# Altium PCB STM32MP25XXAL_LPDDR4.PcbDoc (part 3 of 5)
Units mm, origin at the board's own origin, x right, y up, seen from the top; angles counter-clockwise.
Board outline 125 x 95 mm, 6 copper layers (Top Layer, Signal Layer 1, Signal Layer 2, Signal Layer 3, Signal Layer 4, Bottom Layer), stack 1.403 mm thick; 182 components, 297 nets, 1131 pads, 958 vias.
Unrouted connection lines stored in the file: 5.
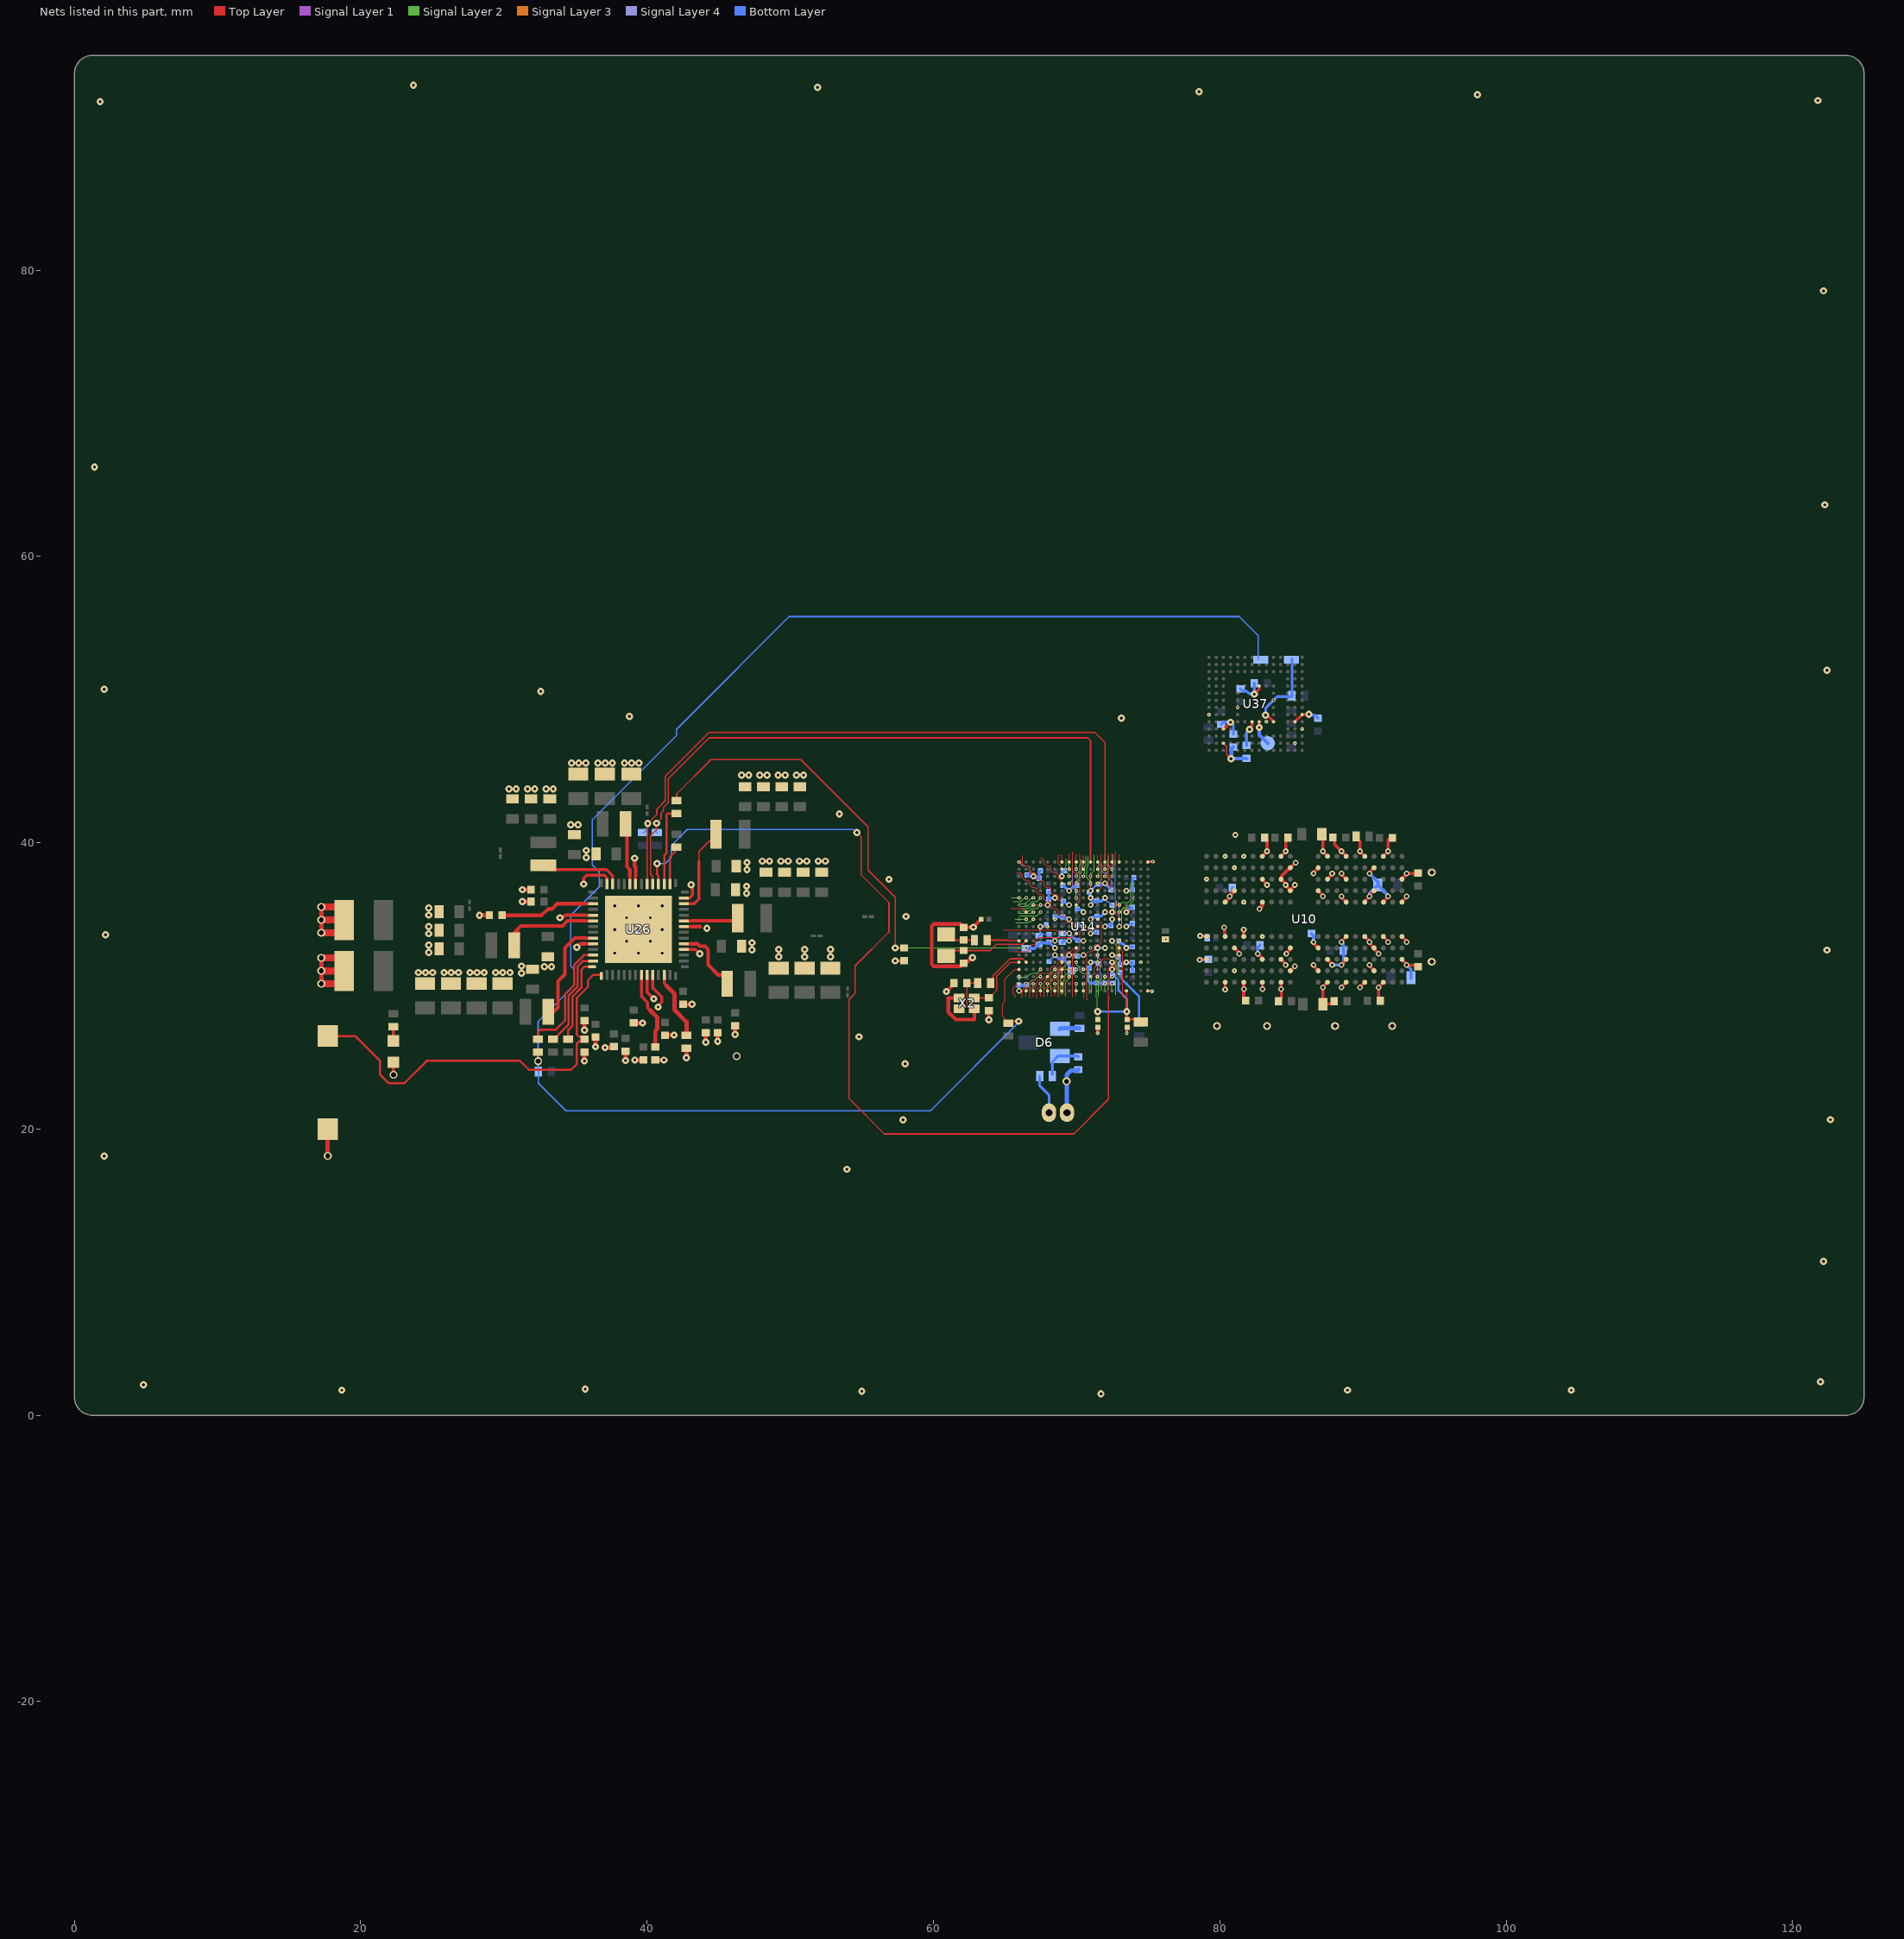
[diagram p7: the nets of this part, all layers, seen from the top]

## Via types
v1: diameter 0.26, hole 0.1, Top Layer to Signal Layer 1, 266 vias
v2: diameter 0.5, hole 0.2, Top Layer to Bottom Layer, 216 vias
v3: diameter 0.26, hole 0.1, Signal Layer 1 to Signal Layer 2, 138 vias
v4: diameter 0.4, hole 0.2, Signal Layer 1 to Signal Layer 4, 99 vias
v5: diameter 0.4, hole 0.2, Top Layer to Bottom Layer, tented both sides, 94 vias
v6: diameter 0.26, hole 0.1, Signal Layer 4 to Bottom Layer, 82 vias
v7: diameter 0.55, hole 0.35, Top Layer to Bottom Layer, 55 vias
v8: diameter 0.55, hole 0.3, Top Layer to Bottom Layer, 7 vias
v9: diameter 0.5, hole 0.2, Signal Layer 1 to Signal Layer 4, 1 vias

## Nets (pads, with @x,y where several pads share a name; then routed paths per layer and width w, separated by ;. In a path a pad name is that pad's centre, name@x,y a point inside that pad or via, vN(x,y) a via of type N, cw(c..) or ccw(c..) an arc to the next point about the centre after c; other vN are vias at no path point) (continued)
GND: B2.1 C1.1 C2.1 C3.1 C4.1 C5.1 C9.1 C14.1 C15.1 C16.1 C17.1 C18.2 C19.1 C20.1 C21.1 C22.1 C23.1 C24.1 C26.1 C27.1 C28.1 C29.1 C30.1 C32.1 C33.1 C34.1 C35.1 C36.1 C37.1 C38.1 C39.1 C40.1 C41.1 C42.2 C43.1 C50.1 C51.1 C52.1 C53.2 C54.2 C55.2 C56.2 C57.2 C58.2 C59.2 C60.2 C61.2 C62.1 C63.1 C64.1 C65.1 C66.1 C67.1 C68.1 C79.1 C81.2 C86.2 C87.1 C90.1 C91.2 C92.2 C117.1 C118.1 C128.1 C130.1 C141.2 C142.2 C152.1 C153.1 C154.1 C155.1 C156.1 C157.1 C175.2 C177.2 C183.1 C184.1 C186.1 C187.1 C188.1 C189.1 C190.2 C191.2 C192.2 C193.1 C194.1 C195.2 C196.1 C197.1 C199.1 C200.1 C201.1 C202.1 C203.2 C204.1 C205.1 C206.1 C207.1 C208.2 C209.1 C210.1 C211.2 C212.1 C213.1 C214.1 C215.1 C217.2 C219.1 C220.1 C225.1 C234.1 C235.1 C236.1 C237.1 C238.1 C240.1 C244.1 C246.1 C248.1 C250.1 C251.1 C253.1 C260.1 C283.1 C284.2 C287.1 C289.1 C299.1 C300.1 C304.2 C306.2 C307.2 CN12.2 LD11.2 R26.1 R57.1 R112.1 U10.A3 U10.A10 U10.AB3 U10.AB5 U10.AB8 U10.AB10 U10.C1 U10.C5 U10.C8 U10.C12 U10.D2 U10.D4 U10.D9 U10.D11 U10.E1 U10.E5 U10.E8 U10.E12 U10.G1 U10.G3 U10.G5 U10.G8 U10.G10 U10.G12 U10.J1 U10.J3 U10.J10 U10.J12 U10.K2 U10.K4 U10.K9 U10.K11 U10.N2 U10.N4 U10.N9 U10.N11 U10.P1 U10.P3 U10.P10 U10.P12 U10.T1 U10.T3 U10.T5 U10.T8 U10.T10 U10.T12 U10.V1 U10.V5 U10.V8 U10.V12 U10.W2 U10.W4 U10.W9 U10.W11 U10.Y1 U10.Y5 U10.Y8 U10.Y12 U14.A1 U14.A19 U14.C3 U14.C7 U14.D13 U14.E8 U14.E16 U14.F6 U14.F11 U14.F13 U14.G8 U14.G11 U14.H10 U14.H13 U14.H16 U14.J6 U14.J8 U14.J11 U14.J14 U14.K4 U14.K5 U14.K10 U14.K13 U14.K16 U14.L8 U14.L11 U14.M6 U14.M10 U14.N11 U14.N13 U14.N16 U14.P6 U14.P8 U14.P10 U14.P14 U14.R11 U14.R16 U14.R18 U14.U1 U14.W1 U14.W19 U26.9 U26.10 U26.18 U26.22 U26.27 U26.36 U26.41 U26.47 U26.52 U26.57 U37.A6 U37.C4 U37.E7 U37.G5 U37.H10 U37.J5 U37.K8 U37.N2 U37.N5 U37.P4 U37.P6 X2.2 X2.4 | length 161.2
  Top Layer w0.09: U10.D2@81.014,31.05 v1(81.025,31.05) ; v1(85.25,46.95) 85.25,46.948 U37.N2@85.251,46.947
  Top Layer w0.1: v2@60.815,29.688 v2(60.901,29.602) ; C92.2@61.431,30.192 C92.2@61.431,30.294 ; v2@62.677,34.095 v2@62.709,34.095 ; U14.W19@74.975,29.65 v1@75.3,29.65
  Top Layer w0.15: v1(79.25,48.95) v1(79.25,48.95) U37.A6@79.251,48.947 ; U10.C1@80.362,30.238 U10.C1@80.371,30.229 ; v5@80.371,29.754 v5(80.375,29.75) ; v1(85.75,47.95) 85.75,47.948 U37.P4@85.751,47.947
  Top Layer w0.2: v7@22.284,23.784 LD11.2@22.284,24.661 ; U26.27@42.568,36.139 42.977,36.139 43.168,36.33 43.168,37.049 v2@43.214,37.095 ; v2(43.068,37.069) v2@43.125,37.012 ; v2(57.325,31.75) 57.925,31.75 C33.1@57.95,31.725 ; v1(71.475,26.7) C214.1@71.475,27.1 ; v1(73.5,26.7) C260.1@73.5,27.1 ; U14.A19@74.975,38.65 74.983,38.65 75.008,38.675 v1(75.325,38.675) ; U37.C4@80.25,47.95 80.256,47.956 80.291,47.956 v2(80.75,48.415) ; v5@80.371,29.754 U10.C1@80.371,30.229 ; v1(81.25,49.45) v1(81.25,49.45) U37.E7@81.251,49.447 ; v2(82.076,47.922) 82.076,48.01 82.251,48.185 U37.G5@82.251,48.447 ; v2(82.401,50.372) 82.751,50.722 U37.H10@82.751,50.947 ; U10.G10@82.975,37.45 82.975,37.41 83.05,37.335 83.05,37.331 83.3,37.081 v5(83.3,37.05) ; v1(83.25,48.45) 83.251,48.449 U37.J5@83.251,48.447 ; v1(83.75,49.95) v1(83.75,49.95) U37.K8@83.751,49.947 ; U37.N5@85.251,48.447 85.751,48.947 85.76,48.956 86.206,48.956 v2(86.225,48.975) ; v5@90.465,36.255 90.488,36.278 90.488,36.363 U10.W9@90.775,36.65
  Top Layer w0.21: v2(35.573,37.114) 35.573,37.514 35.778,37.719 37.007,37.719 37.198,37.528 U26.41@37.198,37.109 ; 35.673,32.939 U26.52@36.228,32.939 ; 35.673,34.939 U26.47@36.228,34.939 ; U26.36@39.198,37.109 39.198,37.664 ; U26.9@39.998,30.769 39.998,29.559 v2(40.466,29.091) ; U26.10@40.398,30.769 40.398,29.873 41.033,29.238 41.033,28.859 40.768,28.595 v2(40.768,28.516) ; U26.18@42.568,32.539 43.37,32.539 v2(43.67,32.239) ; U26.22@42.568,34.139 43.123,34.139
  Top Layer w0.22: v5(78.6,31.815) 78.649,31.815 78.684,31.85 U10.A3@79.075,31.85 ; v5(80.295,34.075) 80.325,34.045 80.325,33.661 80.35,33.636 80.35,33.475 U10.C5@80.375,33.45 ; U10.C1@80.362,30.238 U10.C1@80.375,30.25 ; U10.C8@80.375,35.85 80.695,36.17 80.7,36.17 80.734,36.205 80.734,36.36 U10.D9@81.025,36.65 ; U10.D4@81.025,32.65 81.315,32.36 81.315,32.27 v5@81.35,32.235 ; U10.E1@81.675,30.25 81.675,29.095 C66.1@81.8,28.97 ; U10.E5@81.675,33.45 v5(81.675,33.925) v5@81.675,33.935 ; v5(82.65,32.25) 82.91,31.99 82.91,31.95 82.975,31.885 U10.G3@82.975,31.85 ; v5@82.975,29.76 v5(82.975,29.77) U10.G1@82.975,30.25 ; v1(82.975,33.45) U10.G5@82.98,33.45 ; U10.G12@82.975,39.05 83.3,39.375 v5(83.3,39.4) 83.3,40.051 83.287,40.064 83.287,40.205 C64.1@83.142,40.35 ; C54.2@84.1,28.935 84.1,28.96 84.303,29.164 84.303,29.741 v5(84.275,29.77) U10.J1@84.275,30.25 ; U10.J3@84.275,31.85 84.566,31.559 84.566,31.459 v5@84.6,31.425 ; U10.J10@84.275,37.445 84.609,37.11 v5@84.609,37.095 ; U10.J10@84.275,37.45 84.299,37.475 84.299,37.649 84.9,38.25 U10.K11@84.925,38.25 85.274,38.6 v5(85.3,38.6) ; U10.J12@84.275,39.05 84.279,39.05 v5@84.6,39.37 ; v5(84.6,39.4) 84.6,40.051 84.605,40.056 84.605,40.205 C52.1@84.75,40.35 ; v5@84.644,37.076 84.634,37.066 84.634,36.964 84.925,36.673 U10.K9@84.925,36.65 84.925,36.683 85.25,37.008 v5(85.25,37.05) ; v5(84.65,32.25) 84.65,32.278 84.9,32.528 U10.K4@84.9,32.625 ; U10.K2@84.925,31.05 84.93,31.05 v5(85.25,31.37) ; v5(86.55,31.45) 86.584,31.416 86.584,31.361 U10.N2@86.875,31.071 ; v5@86.55,32.97 86.87,32.65 U10.N4@86.875,32.65 ; v5@86.55,37.92 86.875,38.245 U10.N11@86.875,38.25 ; U10.N9@86.875,36.65 87.165,36.36 87.165,36.285 v5(87.2,36.25) ; C62.1@86.995,40.425 87.15,40.58 87.2,40.53 v5(87.2,39.4) 87.2,39.375 U10.P12@87.525,39.05 ; C63.1@87.2,28.72 v5(87.2,29.9) 87.2,29.92 87.525,30.245 U10.P1@87.525,30.25 ; C63.1@87.2,28.738 87.802,28.738 87.83,28.765 87.855,28.765 88,28.91 C67.1@88,28.935 ; U10.P3@87.525,31.835 87.815,31.545 87.815,31.485 v5(87.85,31.45) ; U10.P10@87.525,37.45 87.845,37.77 v5@87.85,37.77 ; C65.1@87.925,40.36 88.013,40.272 88.013,39.887 v5(88.5,39.4) 88.825,39.075 U10.T12@88.825,39.05 ; v5@88.5,29.92 88.825,30.245 U10.T1@88.825,30.25 ; v5(88.5,31.45) 88.534,31.485 88.534,31.534 88.825,31.824 U10.T3@88.825,31.85 ; v5@88.5,33.12 88.825,33.445 U10.T5@88.825,33.45 ; v5(88.5,36.25) 88.534,36.216 88.534,36.141 U10.T8@88.825,35.85 ; v5@88.5,37.77 88.82,37.45 U10.T10@88.825,37.45 ; R26.1@89.525,40.435 89.525,40.34 R26.1@89.67,40.195 ; R26.1@89.671,40.195 89.8,40.066 v5(89.8,39.4) ; v5@89.8,29.92 90.125,30.245 U10.V1@90.125,30.25 ; v5@89.8,39.375 U10.V12@90.125,39.05 ; U10.V5@90.125,33.45 90.415,33.16 90.415,33.005 90.45,32.97 90.455,32.97 U10.W4@90.775,32.65 90.775,32.615 90.84,32.55 90.84,32.51 v5(91.1,32.25) ; U10.V8@90.125,35.85 90.125,35.885 90.19,35.95 90.19,35.961 90.45,36.221 v5(90.45,36.25) ; v5(90.45,31.45) 90.45,31.403 90.775,31.078 U10.W2@90.775,31.05 ; v5@90.45,37.92 90.775,38.245 U10.W11@90.775,38.25 ; C55.2@91.2,28.95 91.1,29.05 v5(91.1,29.9) 91.1,29.92 91.425,30.245 U10.Y1@91.425,30.25 ; U10.Y5@91.425,33.45 91.425,33.445 v5@91.75,33.12 ; U10.Y8@91.425,35.85 91.425,35.879 91.75,36.204 v5(91.75,36.25) ; U10.Y12@91.425,39.05 91.43,39.05 v5@91.75,39.37 ; v5(91.75,39.4) 91.75,40.031 91.755,40.036 91.755,40.185 C53.2@91.9,40.33 ; U10.AB3@92.725,31.834 93.015,31.544 93.015,31.485 v5(93.05,31.45) ; U10.AB5@92.725,33.45 93.05,33.125 v5@93.05,33.12 ; U10.AB8@92.725,35.85 92.725,35.873 93.015,36.163 93.015,36.205 v5@93,36.22 ; U10.AB10@92.725,37.45 92.725,37.485 92.79,37.55 92.79,37.561 v5@93.078,37.85 ; v5(93.05,37.85) v5@93.078,37.85 ; v5@93.064,31.436 93.748,31.436 C57.2@93.85,31.334 ; v5@93.098,37.87 v5@93.078,37.85 ; C56.2@93.85,37.87 93.83,37.85 v5@93.078,37.85
  Top Layer w0.25: v2(33.906,34.764) 33.954,34.812 34.155,34.812 34.282,34.939 35.673,34.939 ; v2(35.086,32.701) 35.119,32.701 35.357,32.939 35.673,32.939 ; v2(39.123,38.914) 39.123,38.353 39.198,38.278 39.198,37.664 ; 43.123,34.139 43.728,34.139 ; v2@43.655,32.239 v2(43.67,32.239) ; v2(60.901,29.602) 61.301,30.001 61.301,30.062 C92.2@61.431,30.192 ; X2.2@61.806,29.156 61.039,29.156 61.039,28.159 61.559,27.639 62.856,27.639 X2.4@62.856,28.406 ; v2@62.668,31.972 62.396,31.7 62.242,31.7 C86.2@62.112,31.57 62.087,31.57 61.888,31.37 60.023,31.37 59.877,31.517 59.877,34.174 60.023,34.32 61.887,34.32 C81.2@62.112,34.095 62.677,34.095 62.706,34.124 62.799,34.124 C201.1@63.325,34.65 C201.1@63.35,34.675 ; v2(63.865,27.639) C90.1@63.865,28.256
  Top Layer w0.28: R112.1@76.192,33.242 R112.1@76.2,33.25 ; v5@82.75,35.4 82.975,35.625 U10.G8@82.975,35.85
  Top Layer w0.3: v7@17.245,30.151 v7@17.245,31.951 ; v7@17.245,33.713 v7@17.245,35.513 ; B2.1@17.693,19.993 17.693,18.119 v7(17.698,18.114) ; v2(28.293,34.929) C43.1@28.953,34.929 ; v2(31.283,35.889) C40.1@31.893,35.889 ; v2(31.283,36.714) C39.1@31.893,36.714 ; v2@35.623,26.949 C217.2@35.623,27.559 ; v2@35.625,24.719 C155.1@35.625,25.324 ; v2(36.398,25.749) C154.1@36.398,26.354 ; v2(37.063,25.689) C142.2@37.673,25.689 ; v2@38.498,24.829 C141.2@38.498,25.439 ; C153.1@39.073,27.409 v2(39.683,27.409) ; v2(39.138,24.819) C91.2@39.748,24.819 ; C208.2@40.573,24.819 v2(41.183,24.819) ; C209.1@41.248,26.559 v2(41.883,26.559) ; C156.1@42.523,28.709 v2(43.133,28.709) ; v2(42.748,24.979) R57.1@42.748,25.639 ; v2(44.098,26.069) C189.1@44.098,26.729 ; v2(44.923,26.129) C188.1@44.923,26.729 C188.1@44.923,26.789 ; v2(46.143,26.599) 46.146,26.601 46.146,27.201 C190.2@46.148,27.204
  Top Layer w0.5: v7@17.251,30.145 C18.2@18.834,30.145 ; v7@17.251,31.045 C18.2@18.834,31.045 ; v7@17.251,31.957 C18.2@18.834,31.957 ; v7@17.251,33.707 C42.2@18.834,33.707 ; v7@17.251,34.607 C42.2@18.834,34.607 ; v7@17.251,35.519 C42.2@18.834,35.519
  Signal Layer 1 w0.075: v1(65.975,38.65) 66.225,38.4 66.619,38.4 66.726,38.293 66.726,37.897 66.973,37.65 v4(66.975,37.65) ; v4(71.975,37.15) v4@71.974,37.296
  Signal Layer 1 w0.1: v1@70.975,31.521 v4(70.975,31.65)
  Signal Layer 2 w0.2: v4(71.975,36.15) v4@71.991,36.15 ; v4@72.433,34.592 72.475,34.634 v4(72.475,34.65) v4@72.486,34.661 ; v4@73.439,32.661 73.447,32.661 73.475,32.634 v4@73.475,32.625 ; v4@73.446,35.137 v4@73.447,35.139 ; v6(73.475,35.15) 73.486,35.161 v4@73.486,35.186
  Bottom Layer w0.1: C235.1@67.325,33.45 C235.1@67.375,33.5 C235.1@67.45,33.575 ; C235.1@67.45,33.475 C235.1@67.45,33.575 ; C236.1@67.875,34.275 67.875,34.27 67.755,34.15 v1(67.475,34.15) 67.45,34.125 C235.1@67.45,33.575 ; C244.1@68.07,33.605 67.48,33.605 C235.1@67.45,33.575 ; C234.1@68.075,31.7 68.195,31.82 68.195,31.875 68.258,31.938 68.3,31.938 68.47,32.108 v6@68.47,32.15 ; C244.1@68.075,33.6 68.195,33.48 68.444,33.231 68.444,33.181 v6(68.475,33.15) 68.475,33.162 68.613,33.3 68.613,33.305 68.795,33.487 68.795,33.5 68.945,33.65 68.975,33.65 C225.1@68.995,33.65 C225.1@69,33.65 ; C240.1@68.075,35.95 C240.1@68.075,36.08 ; v4(71.975,36.15) 71.975,36.043 72.15,35.868 72.232,35.868 C177.2@72.475,35.625 ; v4(72.475,32.15) 72.482,32.15 72.607,32.025 72.925,32.025 72.925,32 73.05,31.875 C251.1@73.05,31.5 ; C251.1@72.975,31.5 C251.1@73.05,31.5 ; C251.1@73.05,31.475 C251.1@73.05,31.5 ; v4(73.475,31.65) 73.325,31.5 C251.1@73.05,31.5
  Bottom Layer w0.15: C210.1@70.873,36.548 70.98,36.655 71.098,36.773 71.12,36.773 71.212,36.865 71.212,36.887 71.325,37 71.4,37 C287.1@71.5,37.1
  Bottom Layer w0.2: 65.971,29.854 65.971,29.678 65.974,29.675 v6@65.975,29.675 ; C215.1@66.525,37.75 C215.1@66.525,37.745 66.6,37.67 66.605,37.67 66.625,37.65 v4(66.975,37.65) 66.991,37.65 67.105,37.536 67.389,37.536 C237.1@67.396,37.529 ; C237.1@67.38,37.5 67.38,37.95 C220.1@67.48,38.05 ; C240.1@68.045,36.05 C17.1@68.045,36.6 ; C240.1@68.05,36.05 68.05,36.055 68.075,36.08 68.12,36.125 68.125,36.125 68.15,36.15 v4(68.475,36.15) v6@68.491,36.15 ; C240.1@68.05,36.08 C240.1@68.055,36.075 ; v6@68.475,32.143 v6(68.475,32.15) ; v6@68.478,32.146 68.75,31.875 69.157,31.875 69.432,32.15 v6@69.45,32.15 ; C197.1@68.5,34.825 C307.2@69.05,34.825 69.125,34.75 69.359,34.75 69.459,34.65 v4(69.475,34.65) ; C197.1@68.5,34.85 C197.1@68.529,34.879 ; C225.1@68.95,33.675 C225.1@68.975,33.65 ; v4(68.975,37.65) 68.975,37.93 C16.1@69.1,38.055 ; C225.1@69,33.65 v4(69.475,33.65) 69.82,33.305 69.92,33.305 70.05,33.175 70.475,33.175 v6@70.525,33.125 ; C212.1@69.025,37.025 C212.1@69.05,37.025 C212.1@69.125,36.95 ; C300.1@69.05,31.875 69.47,31.455 69.47,31.205 C87.1@69.625,31.05 ; C205.1@69.075,35.925 69.075,35.9 69.125,35.85 69.168,35.85 69.278,35.74 69.369,35.74 69.459,35.65 v6@69.468,35.65 ; C212.1@69.125,36.949 69.242,36.832 69.3,36.832 69.475,36.657 v6(69.475,36.65) 69.775,36.95 69.975,36.95 C219.1@70.05,37.025 ; v4(69.475,32.15) 70,32.15 C195.2@70.075,32.075 ; C195.2@70.05,32.075 C195.2@70.075,32.075 ; C196.1@70.05,34.275 70.108,34.217 70.392,34.217 70.459,34.15 v6(70.475,34.15) ; C213.1@70.05,35.375 70.116,35.309 70.316,35.309 v6(70.475,35.15) ; C195.2@70.125,32.025 C195.2@70.075,32.075 ; v6@70.475,32.15 70.432,32.15 70.357,32.075 C195.2@70.075,32.075 ; C2.1@70.85,31.225 70.825,31.2 70.825,30.312 70.942,30.195 C253.1@71.4,30.195 71.402,30.197 71.948,30.197 C246.1@71.95,30.195 C15.1@72.5,30.195 ; C2.1@70.875,31.25 70.975,31.35 v4(70.975,31.65) 71.328,31.65 71.348,31.63 71.495,31.63 C4.1@71.55,31.575 ; C210.1@70.875,36.575 70.933,36.517 70.933,36.208 70.975,36.166 v4(70.975,36.15) ; v4(70.975,33.65) 70.991,33.65 71.048,33.707 71.352,33.707 C3.1@71.4,33.755 ; v6@70.975,35.675 70.984,35.675 70.986,35.678 70.986,35.686 71.18,35.88 71.325,35.88 C299.1@71.4,35.955 ; v6(70.976,34.65) 70.983,34.65 71.134,34.8 71.425,34.8 71.466,34.841 71.666,34.841 v4(71.975,35.15) ; C299.1@71.375,35.925 71.75,35.925 v6@71.905,36.08 ; C1.1@71.405,32.65 v4(71.974,32.65) ; C287.1@71.5,37.1 71.925,37.1 v4(71.975,37.15) 72.305,36.82 72.305,36.8 72.36,36.745 C191.2@72.38,36.745 ; v4(71.975,34.15) 72.05,34.225 C194.1@72.375,34.225 ; C194.1@72.4,34.225 C194.1@72.375,34.225 ; v4(72.475,34.65) 72.475,34.325 C194.1@72.375,34.225 ; C283.1@72.925,33.15 73.143,32.932 73.252,32.932 73.475,32.709 v4(73.475,32.65) 73.55,32.725 C306.2@73.9,32.725 C306.2@73.925,32.725 ; v4(73.475,31.65) 73.5,31.625 C192.2@73.9,31.625 ; v4(73.475,34.15) 73.491,34.15 73.591,34.25 73.775,34.25 C211.2@73.9,34.375 ; v6(73.475,35.15) 73.8,35.475 C175.2@73.9,35.475 ; v4(73.475,36.65) 73.875,36.65 C304.2@73.925,36.7 ; C304.2@73.825,36.775 C304.2@73.9,36.7 73.9,37.46 C238.1@74,37.56 ; C284.2@73.925,31.025 73.9,31.05 C284.2@73.9,31.075 C192.2@73.9,31.625 ; C192.2@73.925,31.625 C192.2@73.9,31.625 ; C118.1@80.096,48.263 80.261,48.428 80.761,48.428 80.946,48.243 C79.1@80.946,47.588 ; C9.1@81.451,50.763 81.606,50.608 81.845,50.608 82.044,50.409 82.366,50.409 82.411,50.363 C117.1@82.411,51.148 ; C130.1@81.864,46.788 81.864,47.691 v2@82.086,47.913 ; v2@86.25,48.975 86.32,48.905 86.645,48.905 C128.1@86.85,48.7 ; C68.1@86.4,33.65 C68.1@86.55,33.5
  Bottom Layer w0.22: v5(78.6,31.815) 79.165,31.815 C60.2@79.2,31.85 ; v5@80.7,36.25 80.875,36.425 C61.2@80.875,36.85 ; v5@82.65,32.15 82.65,32.7 C59.2@82.8,32.85 ; v5@86.55,33.05 C68.1@86.55,33.5 ; v5(87.85,31.45) v5(88.5,31.45) 88.65,31.601 C58.2@88.65,32.425 ; v5(88.5,33.05) 88.625,32.925 C58.2@88.625,32.45 ; v5(88.5,31.45) v5@88.525,31.425 ; v5@90.45,36.225 90.45,36.475 C51.1@91.025,37.05 C51.1@91.075,37 ; v5(90.45,37.85) 91.075,37.225 C51.1@91.075,37 ; v5@91.775,36.225 91.775,36.3 C51.1@91.075,37 ; v5(93.05,31.45) 93.35,31.15 C50.1@93.35,30.575 C50.1@93.35,30.525
  Bottom Layer w0.28: C248.1@65.95,30.05 C250.1@66.5,30.05
  Bottom Layer w0.3: CN12.2@69.325,20.734 69.325,23.3 v7(69.3,23.325) 69.31,23.335 69.31,23.802 69.602,24.094 70.06,24.094 C14.1@70.117,24.151
  other v1: 75.275,29.625 65.975,29.65 65.975,30.65 70.975,31.65 73.475,31.65 74.475,31.65 68.475,32.15 69.475,32.15 70.474,32.149 72.475,32.15 70.974,32.649 71.974,32.65 73.475,32.65 68.475,33.15 70.475,33.15 76.225,33.25 69.475,33.65 70.975,33.65 67.975,34.15 70.475,34.15 71.975,34.15 73.475,34.15 68.475,34.65 69.475,34.65 70.976,34.65 72.475,34.65 70.475,35.15 71.975,35.15 73.475,35.15 69.475,35.65 70.975,35.65 81.675,35.85 68.475,36.15 70.975,36.15 71.975,36.15 69.475,36.65 73.475,36.65 71.975,37.15 79.075,37.45 66.975,37.65 68.975,37.65 81.025,38.25 80.375,39.05 81.675,39.05
  other v2: 71.7,1.5 55,1.675 18.675,1.75 88.925,1.75 104.55,1.75 35.675,1.825 4.825,2.125 121.95,2.35 122.175,10.75 53.961,17.189 2.075,18.1 57.873,20.639 122.65,20.65 58.023,24.564 35.62,24.749 38.498,24.779 54.8,26.444 35.623,26.899 31.223,30.889 24.022,30.937 24.523,30.937 25.024,30.937 25.822,30.937 26.323,30.937 26.824,30.937 27.622,30.937 28.123,30.937 28.624,30.937 29.422,30.937 29.923,30.937 30.424,30.937 32.822,31.341 33.323,31.341 31.223,31.389 62.725,31.972 49.202,32.039 51.002,32.039 52.802,32.039 37.748,32.289 39.398,32.289 41.048,32.289 24.748,32.339 47.318,32.514 122.4,32.5 49.202,32.54 51.002,32.54 52.802,32.54 24.748,32.839 47.318,33.014 38.573,33.114 40.223,33.114 2.175,33.575 24.748,33.639 37.748,33.939 39.398,33.939 41.048,33.939 44.178,34.014 62.78,34.095 24.748,34.139 38.573,34.764 40.223,34.764 58.087,34.852 24.748,34.939 24.748,35.439 37.748,35.589 39.398,35.589 41.048,35.589 46.948,36.464 46.948,36.964 56.893,37.444 46.973,38.114 46.973,38.614 48.048,38.714 48.548,38.714 49.348,38.714 49.848,38.714 50.648,38.714 51.148,38.714 51.948,38.714 52.448,38.714 35.748,38.962 35.748,39.462 34.673,41.262 35.174,41.262 53.433,42.004 30.348,43.762 30.849,43.762 31.648,43.762 32.149,43.762 32.948,43.762 33.449,43.762 46.598,44.714 47.098,44.714 47.873,44.714 48.373,44.714 49.148,44.714 49.648,44.714 50.423,44.714 50.923,44.714 34.722,45.564 35.223,45.564 35.724,45.564 36.572,45.564 37.073,45.564 37.574,45.564 38.422,45.564 38.923,45.564 39.424,45.564 73.125,48.7 38.773,48.814 32.573,50.576 2.075,50.725 122.4,52.05 122.25,63.6 1.4,66.25 122.175,78.55 1.8,91.775 121.775,91.85 98,92.25 78.55,92.475 51.9,92.775 23.675,92.925
  other v4: 65.975,29.65 68.475,32.15 70.474,32.149 68.475,33.15 70.475,33.15 67.475,34.15 70.475,34.15 70.976,34.65 70.475,35.15 73.475,35.15 69.475,35.65 70.975,35.65 69.475,36.65
  other v5: 81.686,29.775 88.5,29.9 89.8,29.9 84.6,31.45 81.35,32.25 86.55,33.05 90.45,33.05 91.75,33.05 93.05,33.05 82.775,35.375 80.7,36.25 93.05,36.25 84.6,37.05 86.55,37.85 87.85,37.85 88.5,37.85 81.075,40.55
  other v6: 65.975,29.65 70.975,31.65 73.475,31.65 69.475,32.15 70.474,32.149 72.475,32.15 71.975,32.65 73.475,32.65 70.475,33.15 69.475,33.65 70.975,33.65 67.475,34.15 71.975,34.15 73.475,34.15 69.475,34.65 72.475,34.65 71.975,35.15 69.475,35.65 70.975,35.65 68.475,36.15 70.975,36.15 71.975,36.15 73.475,36.65 71.975,37.15 66.975,37.65 68.975,37.65
  other v7: 22.285,23.787 46.248,25.084 17.246,30.153 17.246,31.053 17.246,31.953 17.246,33.715 17.246,34.615 17.246,35.515
  other v8: 79.8,27.185 83.3,27.185 88.05,27.185 92.05,27.185 94.8,31.685 94.8,37.935
HSE_IN: C90.2 U14.R1 X2.1 | length 4.8
  Top Layer w0.1: X2.1@62.856,29.156 C90.2@63.89,29.156 ; C90.2@63.865,29.156 C90.2@63.89,29.156 ; U14.R1@65.975,31.65 65.575,31.65 65.372,31.65 64.425,30.703 64.425,29.691 C90.2@63.89,29.156
HSE_OUT: R3.2 U14.R2 | length 3.5
  Top Layer w0.1: R3.2@63.981,30.192 64.162,30.373 64.162,30.721 ; 64.175,30.725 65.35,31.9 66.225,31.9 U14.R2@66.475,31.65
I2C7.SCL: R261.1 U14.A11 U26.33 | length 47.8
  Top Layer w0.1: U26.33@40.398,37.109 40.398,37.639 40.248,37.789 40.248,40.498 40.661,40.911 v2(40.661,41.364) ; v2@40.75,41.375 40.75,41.453 40.984,41.687 40.984,42.084 41.15,42.25 ; 41.146,42.25 41.146,42.475 41.475,42.804 41.475,44.464 44.336,47.325 70.775,47.325 70.975,47.125 U14.A11@70.975,38.65
  Bottom Layer w0.1: v2@40.641,41.364 40.641,40.763 R261.1@40.684,40.72
I2C7.SDA: R260.1 U14.A13 U26.34 | length 49.4
  Top Layer w0.1: U26.34@39.998,37.109 v2@39.998,41.298 ; v2(40.05,41.35) 40.674,41.974 40.674,42.344 41.269,42.938 41.269,44.644 44.325,47.7 71.275,47.7 71.975,47 U14.A13@71.975,38.65
  Bottom Layer w0.1: R260.1@39.709,40.72 39.799,40.72 39.979,40.9 39.979,41.279 v2(40.05,41.35)
JTDI: U14.W3 | length 0.4
  Top Layer w0.075: 66.975,29.225 U14.W3@66.975,29.65
JTDO_TRACESWO: U14.V1 | length 1.2
  Top Layer w0.075: 65.7,29.2 65.7,29.339 65.56,29.478 65.56,29.822 65.803,30.064 65.814,30.064 65.87,30.12 65.945,30.12 U14.V1@65.975,30.15
JTMS_SWCLK: U14.W4 | length 0.4
  Top Layer w0.075: 67.475,29.225 U14.W4@67.475,29.65
JTMS_SWDIO: U14.W2 | length 0.4
  Top Layer w0.075: 66.475,29.25 U14.W2@66.475,29.65
LVDS1_D0N: U14.F1 | length 0.6
  Top Layer w0.075: U14.F1@65.95,36.125 v3(65.975,36.15)
  Signal Layer 2 w0.075: 65.45,36.15 v3(65.975,36.15)
  other v1: 65.975,36.15
LVDS1_D0P: U14.F2 | length 1
  Signal Layer 2 w0.075: 65.575,35.9 66.101,35.9 66.316,36.116 66.441,36.116 v3(66.475,36.15)
  other v1: 66.475,36.15
LVDS1_D1N: U14.F3 | length 1.2
  Signal Layer 2 w0.075: 65.95,35.735 66.413,35.735 66.792,36.115 66.94,36.115 v3(66.975,36.15)
  other v1: 66.975,36.15
LVDS1_D1P: U14.F4 | length 1.7
  Signal Layer 2 w0.075: 66.054,35.565 66.57,35.565 66.726,35.72 66.726,35.753 66.872,35.899 67.087,35.899 67.225,35.899 v3(67.475,36.15)
  other v1: 67.475,36.15
LVDS1_D2N: U14.G3 | length 1
  Signal Layer 2 w0.075: 66.123,35.4 66.639,35.4 66.803,35.564 66.839,35.564 66.925,35.65 v3(66.975,35.65)
  other v1: 66.975,35.65
LVDS1_D2P: U14.G4 | length 1.5
  Signal Layer 2 w0.075: 66.175,35.235 66.707,35.235 66.872,35.399 66.908,35.399 67.226,35.399 v3(67.475,35.649)
  other v1: 67.475,35.649
LVDS1_D3N: U14.J2 | length 0.8
  Signal Layer 2 w0.075: 65.725,34.65 v3(66.475,34.65)
  other v1: 66.475,34.65
LVDS1_D3P: U14.J3 | length 1.3
  Signal Layer 2 w0.075: 65.75,34.4 66.578,34.4 66.678,34.5 66.825,34.5 v3(66.975,34.65)
  other v1: 66.975,34.65
LVDS1_D4N: U14.H3 | length 1
  Signal Layer 2 w0.075: 66.032,35.07 66.845,35.07 66.925,35.15 v3(66.975,35.15)
  other v1: 66.975,35.15
LVDS1_D4P: U14.H4 | length 1.6
  Signal Layer 2 w0.075: 65.968,34.901 67.226,34.901 v3(67.475,35.15)
  other v1: 67.475,35.15
MP257_WAKEUP: U14.P15 U26.32 | length 68.3
  Top Layer w0.075: 72.225,29.275 72.225,31.253 72.372,31.4 72.577,31.4 72.732,31.555 72.732,31.907 U14.P15@72.975,32.15
  Top Layer w0.1: v2(54.649,40.719) 54.961,40.408 54.961,37.743 56.893,35.811 56.893,33.768 54.529,31.404 54.529,29.487 54.098,29.055 54.098,22.132 56.566,19.663 69.813,19.663 72.229,22.079 72.229,29.271
  Top Layer w0.15: v2(40.698,38.539) 40.698,37.792 40.798,37.692 U26.32@40.798,37.109
  Bottom Layer w0.1: v2@40.679,38.54 41.26,38.54 41.679,38.96 41.679,39.798 42.797,40.915 54.442,40.915 54.639,40.717 v2@54.65,40.717
NetB2_2: B2.2 C155.2 U26.1 | length 28.3
  Top Layer w0.15: B2.2@17.693,26.493 19.619,26.493 21.336,24.776 21.336,23.812 21.934,23.214 23.06,23.214 24.611,24.764 31.117,24.764 31.743,24.138 34.697,24.138 35.098,24.539 35.098,25.964 35.245,26.111 35.452,26.111 C155.2@35.625,26.284 35.46,26.449 35.236,26.449 35.086,26.599 35.086,29.147 35.86,29.922 35.86,30.376 36.253,30.769 U26.1@36.798,30.769
NetC14_2: C14.2 D6.2 R66.2 | length 2.9
  Bottom Layer w0.2: R66.2@68.307,23.82 68.307,24.692 68.707,25.092 D6.2@68.826,25.092 70.075,25.092 C14.2@70.117,25.051
NetC15_2: C15.2 C214.2 C260.2 R11.2 U14.T14 U14.U12 U14.W16 | length 11.6
  Top Layer w0.075: C214.2@71.45,27.675 71.475,27.7 v2(71.475,28.2)
  Top Layer w0.09: U14.W16@73.475,29.65 73.475,28.225 v2(73.5,28.2) ; C260.2@73.5,27.8 73.5,27.675 C260.2@73.525,27.65 ; R11.2@74.32,27.45 R11.2@74.525,27.45
  Top Layer w0.15: C260.2@73.5,27.8 v2(73.5,28.2) ; C260.2@73.525,27.65 74.12,27.65 R11.2@74.32,27.45
  Signal Layer 2 w0.075: v2(71.475,28.2) 71.425,28.25 71.425,29.128 71.382,29.171 71.382,30.514 71.475,30.607 v3(71.475,30.65)
  Bottom Layer w0.1: C15.2@72.475,30.775 v4(72.475,31.15)
  Bottom Layer w0.15: v2@71.45,28.2 v2(71.475,28.2) v2(73.5,28.2) ; C15.2@72.5,30.745 72.6,30.645 72.678,30.645 72.918,30.405 72.918,29.682 73.525,29.075 v2@73.525,28.2
  other v1: 71.475,30.65 72.475,31.15
  other v6: 72.475,31.15
NetC43_2: C43.2 U26.45 | length 6.7
  Top Layer w0.21: 35.673,35.739 U26.45@36.228,35.739
  Top Layer w0.25: C43.2@29.913,34.929 32.629,34.929 33.074,35.374 33.349,35.374 33.714,35.739 35.673,35.739
NetC79_2: C79.2 C130.2 U37.C2 | length 3.3
  Top Layer w0.09: U37.C2@80.251,46.947 80.253,46.947 80.492,46.708 80.492,46.158 v2(80.775,45.875)
  Bottom Layer w0.25: C79.2@80.946,46.688 80.941,46.688 80.811,46.558 80.811,45.911 v2(80.775,45.875) 80.782,45.882 81.857,45.882 C130.2@81.864,45.888
NetC81_1: C81.1 R64.2 X1.1 | length 2.1
  Top Layer w0.1: X1.1@60.886,33.595 61.286,33.195 C81.1@62.112,33.195 R64.2@62.862,33.195
NetC92_1: C92.1 R3.1 X2.3 | length 2.9
  Top Layer w0.1: X2.3@61.806,28.406 62.033,28.633 62.265,28.633 62.331,28.699 C92.1@62.331,30.192 R3.1@63.081,30.192
NetC208_1: C208.1 U26.8 | length 5.4
  Top Layer w0.21: U26.8@39.598,30.769 39.598,29.273 40.023,28.848 40.023,28.484 40.196,28.311
  Top Layer w0.3: 40.196,28.311 40.698,27.809 40.698,26.982 40.573,26.856 C208.1@40.573,25.844
NetC225_2: C225.2 U14.M8 | length 0.5
  Bottom Layer w0.2: C225.2@69,33.025 69.125,33.15 v6(69.475,33.15)
  other v1: 69.475,33.15
  other v4: 69.475,33.15
NetC235_2: C235.2 C244.2 R267.1 U14.N6 | length 2.4
  Bottom Layer w0.2: R267.1@66.5,32.6 67.075,32.6 67.225,32.75 67.225,32.8 67.325,32.9 C235.2@67.375,32.9 67.475,33 68.015,33 C244.2@68.07,33.055 ; C244.2@68.075,33.05 v6(68.475,32.65)
  other v1: 68.475,32.65
  other v4: 68.475,32.65
NetC251_2: C251.2 R286.2 U14.R14 U14.U11 | length 7.6
  Top Layer w0.075: U14.U11@70.95,30.6 71.224,30.874 71.224,31.244 71.378,31.397 71.575,31.397 71.725,31.547 71.725,31.753 71.872,31.899 72.226,31.899 v4(72.475,31.65)
  Bottom Layer w0.1: v4(72.475,31.65) 72.743,31.382 72.743,31.232 C251.2@73.05,30.925
  Bottom Layer w0.15: C251.2@73.05,30.925 73.15,30.825 73.15,30.475 74.35,29.275 R286.2@74.35,27.35
  other v1: 72.475,31.65
  other v6: 72.475,31.65
NetCN12_1: CN12.1 R66.1 | length 3.2
  Bottom Layer w0.2: R66.1@67.416,23.699 67.416,23.033 68.074,22.375 CN12.1@68.074,20.815
NetD6_1: D6.1 R67.1 | length 1.4
  Bottom Layer w0.3: D6.1@68.826,26.992 68.874,27.041 R67.1@70.199,27.041
NetD7_1: D7.1 R248.1 U37.K5 | length 6
  Top Layer w0.2: v2@83.201,48.997 U37.K5@83.751,48.447
  Bottom Layer w0.2: v2@83.201,48.997 83.213,49.009 83.213,49.413 84,50.2 85.025,50.2 R248.1@85.075,50.25 ; D7.1@85.031,52.846 85.043,52.834 R248.1@85.043,50.263
  other v2: 83.2,48.915
NetL1_1: L1.1 U26.37 | length 4.2
  Top Layer w0.21: U26.37@38.798,37.109 38.798,37.664
  Top Layer w0.25: L1.1@38.598,41.274 38.598,38.312 38.798,38.112 38.798,37.664
NetL2_1: L2.1 U26.26 | length 6
  Top Layer w0.09: 43.623,38.699 43.623,39.399 44.331,40.107 44.458,40.107 44.813,40.462 L2.1@44.813,40.589
  Top Layer w0.2: U26.26@42.815,35.739 43.298,35.739 43.623,36.064 43.623,38.699
NetL3_1: L3.1 U26.40 | length 5.9
  Top Layer w0.15: L3.1@32.596,38.301 L3.1@32.748,38.149
  Top Layer w0.21: L3.1@32.748,38.414 33.033,38.129 34.808,38.129 ; 34.808,38.129 37.163,38.129 37.598,37.694 U26.40@37.598,37.109
NetL4_1: L4.1 U26.23 | length 3.8
  Top Layer w0.15: L4.1@46.258,34.024 L4.1@46.258,34.539
  Top Layer w0.21: U26.23@42.568,34.539 43.123,34.539
  Top Layer w0.25: 43.123,34.539 45.898,34.539
NetL5_1: L5.1 U26.48 | length 7.2
  Top Layer w0.15: L5.1@30.516,32.587 L5.1@30.768,32.839 ; L5.1@30.988,32.724 L5.1@30.988,33.239
  Top Layer w0.21: 35.673,34.539 U26.48@36.228,34.539
  Top Layer w0.25: 30.723,33.739 31.173,34.189 34.098,34.189 34.448,34.539 35.673,34.539 ; L5.1@30.988,33.239 30.988,33.754
NetL6_1: L6.1 U26.19 | length 4.9
  Top Layer w0.21: U26.19@42.568,32.939 43.123,32.939
  Top Layer w0.25: 43.123,32.939 43.521,32.939 43.696,32.764 44.048,32.764 44.273,32.539 44.273,31.464 44.969,30.768 45.323,30.768 45.328,30.763 L6.1@45.328,30.164
NetL7_1: L7.1 U26.51 | length 7.4
  Top Layer w0.21: 35.673,33.339 U26.51@36.228,33.339
  Top Layer w0.25: L7.1@33.323,28.564 L7.1@33.323,28.808 ; L7.1@33.373,28.089 33.773,28.489 33.773,30.323 34.248,30.798 34.248,32.642 34.945,33.339 35.673,33.339
NetLD11_1: LD11.1 R210.2 | length 1
  Top Layer w0.2: LD11.1@22.284,26.161 R210.2@22.284,27.154
NetR2_2: R2.2 U26.56 | length 6.1
  Top Layer w0.15: R2.2@34.478,26.284 34.478,26.899 34.773,27.194 34.773,29.23 35.41,29.867 35.41,31.124 35.625,31.339 U26.56@36.153,31.339
NetR46_2: R46.2 U26.30 | length 2.8
  Top Layer w0.15: U26.30@41.598,37.109 41.598,39.009 41.93,39.341 41.93,39.569 R46.2@42.048,39.687
NetR57_2: R57.2 U26.12 | length 4.9
  Top Layer w0.21: U26.12@41.198,30.769 41.198,30.155 41.368,29.984
  Top Layer w0.3: 41.368,29.984 41.923,29.43 41.923,28.313 42.748,27.488 R57.2@42.748,26.539
NetR59_2: R59.2 U26.54 | length 8.5
  Top Layer w0.15: R59.2@32.378,26.284 32.378,26.779 32.548,26.949 33.634,26.949 34.273,27.588 34.273,29.437 34.91,30.074 34.91,31.474 35.575,32.139 U26.54@36.228,32.139
NetR60_2: R60.2 U26.55 | length 7.1
  Top Layer w0.15: R60.2@33.428,26.284 33.502,26.284 34.523,27.305 34.523,29.333 35.16,29.971 35.16,31.371 35.529,31.739 U26.55@36.228,31.739
NetR81_2: R81.2 U26.31 | length 5.7
  Top Layer w0.15: U26.31@41.198,37.109 41.198,39.112 41.348,39.262 41.348,41.949 41.436,42.037 R81.2@42.061,42.037
NetR94_1: R94.1 U10.A5 | length 1
  Top Layer w0.2: v5(78.625,33.49) 78.679,33.49 78.717,33.452 79.073,33.452 U10.A5@79.075,33.45
  Bottom Layer w0.22: v5(78.625,33.49) 78.659,33.456 79.035,33.456 79.125,33.366 R94.1@79.125,33.35
NetTP21_1: TP21.1 U37.H5 | length 1.7
  Top Layer w0.15: v2(82.751,48.047) U37.H5@82.751,48.447
  Bottom Layer w0.25: v2@82.761,48.038 82.761,47.539 TP21.1@83.352,46.948
NJTRST: U14.V2 | length 0.6
  Signal Layer 2 w0.075: v3(66.475,30.15) 66.509,30.116 66.509,29.562
  other v1: 66.475,30.15
NRST: C33.2 R81.1 U14.N2 | length 35.9
  Top Layer w0.1: R81.1@42.061,42.937 42.061,43.412 44.463,45.814 50.736,45.814 55.439,41.111 55.439,38.088 57.328,36.199 57.328,32.653 v2(57.325,32.65) 57.95,32.65 C33.2@57.975,32.625
  Signal Layer 2 w0.075: v2(57.325,32.65) v3(66.475,32.65)
  other v1: 66.475,32.65
NRSTC1MS: D7.2 R27.1 R59.1 R272.1 U14.T1 | length 118.3
  Top Layer w0.075: R27.1@65.213,27.513 65.106,27.513 65.001,27.617 65.001,27.724 64.85,27.875 64.85,28.75 64.998,28.898 64.998,30.473 65.675,31.15 U14.T1@65.975,31.15
  Top Layer w0.1: R59.1@32.378,25.384 32.373,25.379 32.373,24.764 v7@32.388,24.749 ; R27.1@65.225,27.525 v2(65.95,27.525)
  Bottom Layer w0.1: R272.1@32.4,24 32.4,23.2 34.325,21.275 59.784,21.275 65.95,27.441 v2(65.95,27.525) ; R272.1@32.404,24.019 32.404,24.732 32.389,24.747 32.389,27.505 34.91,30.026 34.91,31.138 34.66,31.388 34.66,34.935 36.647,36.922 36.647,37.978 36.175,38.45 36.175,41.6 42.05,47.475 42.05,47.925 42.856,48.731 42.856,48.738 49.918,55.8 81.36,55.8 82.685,54.475 D7.2@82.685,52.788
  other v7: 32.388,24.739
OSC32_IN: C86.1 U14.M2 X1.2 | length 6
  Top Layer w0.1: X1.2@60.886,32.095 61.26,32.47 C86.1@62.112,32.47 63.97,32.47 64.4,32.9 66.225,32.9 U14.M2@66.475,33.15
OSC32_OUT: R64.1 U14.M1 | length 2.2
  Top Layer w0.1: R64.1@63.762,33.195 65.23,33.195 65.275,33.15 U14.M1@65.975,33.15
PA1: U14.N15 | length 3.5
  Top Layer w0.075: U14.N15@72.975,32.65 73.225,32.4 73.225,29.249
PA2: U14.N12 | length 1.6
  Signal Layer 3 w0.075: 71.45,31.075 71.475,31.1 v1(71.475,32.65)
  other v4: 71.475,32.65
PA3: U14.R12 | length 2.6
  Signal Layer 2 w0.075: v3(71.475,31.65) 71.636,31.489 71.636,30.842 71.724,30.753 71.724,30.547 71.539,30.361 71.539,29.236
  other v1: 71.475,31.65
PA4: U14.P12 | length 2.4
  Signal Layer 1 w0.075: v1(71.475,32.15) 71.475,32.003 71.724,31.753 71.724,31.351 71.656,31.282 71.656,30.822 71.724,30.753 71.724,30.497 71.675,30.448 71.675,29.95
PA5: U14.J12 | length 6.4
  Top Layer w0.075: 70.775,29.025 70.725,29.074 70.725,32.276 70.849,32.399 71.077,32.399 71.225,32.547 71.225,32.753 71.373,32.901 71.578,32.901 71.725,33.047 71.725,34.4 U14.J12@71.475,34.65
PA6: U14.M14 | length 2.4
  Signal Layer 3 w0.075: v3(72.475,33.15) 72.475,33.127 72.813,32.789 72.813,30.845
  other v1: 72.475,33.15
  other v4: 72.475,33.15
PA7: U14.K15 | length 6.6
  Signal Layer 3 w0.075: v3(72.975,34.15) 73.156,34.331 73.156,35.282 73.343,35.469 73.619,35.469 73.625,35.475
  Bottom Layer w0.075: 72.65,38.8 72.718,38.732 72.718,37.099 72.688,37.069 72.688,36.531 72.718,36.501 72.718,35.982 72.975,35.725 v3(72.975,34.15)
  other v1: 72.975,34.15
  other v4: 72.975,34.15
  other v6: 72.975,34.15
PA8: U14.K9 | length 6.5
  Top Layer w0.075: 65.85,37.9 66.076,37.9 66.224,37.752 66.224,37.548 66.372,37.4 66.578,37.4 66.725,37.253 66.725,37.047 66.872,36.9 67.078,36.9 67.225,36.753 67.225,36.547 67.372,36.401 67.577,36.401 67.725,36.252 67.725,36.047 67.872,35.9 68.078,35.9 68.225,35.753 68.225,35.547 68.372,35.401 68.475,35.401 ; 68.475,35.399 68.578,35.399 68.724,35.253 68.724,35.054 68.886,34.892 69.078,34.892 69.226,34.745 69.226,34.547 69.372,34.401 69.724,34.401 U14.K9@69.975,34.15
PA9: U14.K12 | length 6.3
  Top Layer w0.075: 69.725,29.225 69.725,32.253 69.88,32.407 70.075,32.407 70.218,32.55 70.218,33.745 70.372,33.899 71.224,33.899 U14.K12@71.475,34.15
PA10: U14.M15 | length 3.9
  Signal Layer 2 w0.075: 72.725,29.375 72.725,30.753 72.9,30.928 72.9,31.3 72.975,31.375 v1(72.975,33.15)
  other v3: 72.975,33.15
PA11: U14.R9 | length 2.7
  Signal Layer 2 w0.075: v3(69.975,31.65) 69.984,31.641 69.984,31.466 70.05,31.4 70.078,31.4 70.225,31.253 70.225,31.047 70.372,30.901 70.502,30.901 70.503,30.899 70.578,30.899 70.784,30.694 70.784,30.416 70.886,30.314 70.886,29.442
  other v1: 69.975,31.65
PA12: U14.R8 | length 2.5
  Signal Layer 2 w0.075: 68.736,29.55 68.736,31.033 69.01,31.307 69.132,31.307 v3(69.475,31.65)
  other v1: 69.475,31.65
PA13: U14.W9 | length 0.4
  Top Layer w0.075: 69.975,29.275 U14.W9@69.975,29.65
PA14: U14.T8 | length 2.2
  Signal Layer 2 w0.075: 68.893,29.417 68.893,30.527 68.987,30.62 68.987,31.062 69.075,31.15 v3(69.475,31.15)
  other v1: 69.475,31.15
PA15: U14.T10 | length 2
  Signal Layer 2 w0.075: v3(70.475,31.15) 70.682,31.15 70.725,31.106 70.725,31.047 70.944,30.828 70.944,30.606 71.043,30.507 71.043,29.507
  other v1: 70.475,31.15
PB0: U14.B8 | length 0.6
  Signal Layer 2 w0.075: v3(69.475,38.15) 69.475,38.775
  other v1: 69.475,38.15
PB1: U14.D9 | length 1.4
  Signal Layer 1 w0.075: v1(69.975,37.15) 70.225,37.4 70.225,38.4
PB2: U14.E9 | length 1.8
  Signal Layer 1 w0.075: 69.725,38.375 69.725,36.9 v1(69.975,36.65)
PB3: U14.A9 | length 0.5
  Top Layer w0.075: 69.95,39.175 69.975,39.15 U14.A9@69.975,38.65
PB4: U14.C9 | length 1.3
  Signal Layer 2 w0.075: v3(69.975,37.65) 70.01,37.685 70.01,37.81 70.23,38.03 70.23,38.471 70.315,38.555 70.315,38.8
  other v1: 69.975,37.65
PB5: U14.B9 | length 0.9
  Signal Layer 2 w0.075: v3(69.975,38.15) 69.975,39.075
  other v1: 69.975,38.15
PB6: U14.C8 | length 1.3
  Signal Layer 2 w0.075: 69.275,38.875 69.275,38.352 69.226,38.303 69.226,38.047 69.475,37.797 v3(69.475,37.65)
  other v1: 69.475,37.65
PB7: U14.D7 | length 2.7
  Top Layer w0.075: 67.449,38.933 67.483,38.899 67.578,38.899 67.725,38.753 67.725,38.547 67.872,38.4 68.078,38.4 68.225,38.253 68.225,38.047 68.372,37.9 68.578,37.9 68.726,37.752 68.726,37.547 68.963,37.309 68.963,37.137 U14.D7@68.975,37.125
PB8: U14.A7 | length 0.5
  Top Layer w0.075: U14.A7@68.975,38.65 68.975,39.15
PB9: U14.A8 | length 0.5
  Top Layer w0.075: U14.A8@69.475,38.65 69.475,39.175
PB10: U14.E12 | length 3
  Top Layer w0.075: U14.E12@71.475,36.65 71.724,36.9 71.724,38.252 71.888,38.415 72.072,38.415 72.225,38.568 72.225,39.25
PB11: U14.B7 | length 1.1
  Top Layer w0.075: 68.8,39.15 68.732,39.082 68.732,38.55 68.945,38.337 68.945,38.18 U14.B7@68.975,38.15
PB12: U14.E14 | length 2.4
  Signal Layer 1 w0.075: 71.726,38.599 71.726,38.047 71.873,37.899 72.078,37.899 72.226,37.752 72.226,37.547 72.475,37.297 v1@72.475,36.648
  other v1: 72.475,36.65
PB13: U14.G15 | length 2.1
  Signal Layer 2 w0.075: v3(72.975,35.65) 73.156,35.83 73.607,35.83 73.794,36.018 73.794,37.175
  other v1: 72.975,35.65
PB14: U14.H15 | length 2.6
  Signal Layer 2 w0.075: v3(72.975,35.15) 73.305,35.48 73.505,35.48 73.975,35.951 73.975,37.175
  other v1: 72.975,35.15
PB15: U14.J15 | length 5.4
  Top Layer w0.075: 72.7,39.35 72.71,39.34 72.71,38.553 72.572,38.415 72.388,38.415 72.226,38.253 72.226,37.068 72.378,36.915 72.562,36.915 72.726,36.752 72.726,35.047 72.975,34.797 U14.J15@72.975,34.65
PC0: U14.V9 | length 0.6
  Signal Layer 2 w0.075: 69.975,29.55 v3(69.975,30.15)
  other v1: 69.975,30.15
PC1: U14.V10 | length 0.6
  Signal Layer 2 w0.075: 70.475,29.6 v3(70.475,30.15)
  other v1: 70.475,30.15
PC2: U14.T9 | length 1.6
  Signal Layer 2 w0.075: 69.725,29.65 69.725,30.75 ; 69.726,30.75 69.726,30.753 69.872,30.899 69.875,30.899 69.954,30.979 69.954,31.129 v3(69.975,31.15)
  other v1: 69.975,31.15
PC3: U14.U4 | length 1.5
  Signal Layer 2 w0.075: 66.725,29.625 66.725,30.253 66.873,30.401 67.078,30.401 67.224,30.547 67.224,30.549 67.304,30.629 67.454,30.629 v3(67.475,30.65)
  other v1: 67.475,30.65
PC4: U14.V3 | length 0.6
  Signal Layer 2 w0.075: 66.975,29.6 v3(66.975,30.15)
  other v1: 66.975,30.15
PC5: U14.T7 | length 2.7
  Top Layer w0.075: 67.725,29.225 67.74,29.241 67.74,29.542 67.732,29.55 67.732,29.75 67.875,29.892 67.899,29.892 67.904,29.897 68.075,29.897 68.225,30.048 68.225,30.253 68.373,30.401 68.578,30.401 68.73,30.552 68.73,30.748 68.889,30.907 68.889,31.029 68.975,31.114 U14.T7@68.975,31.15
PC6: U14.R7 | length 3.6
  Top Layer w0.075: 67.225,29.125 67.225,29.756 67.366,29.897 67.575,29.897 67.726,30.048 67.726,30.253 67.88,30.407 68.081,30.407 68.222,30.549 68.222,30.75 68.372,30.899 68.577,30.899 68.724,31.047 68.724,31.253 68.962,31.491 68.962,31.637 U14.R7@68.975,31.65
PC7: U14.W5 | length 0.4
  Top Layer w0.075: 67.975,29.3 U14.W5@67.975,29.65
PC8: U14.U6 | length 1.1
  Signal Layer 2 w0.075: 68.225,29.7 68.225,30.401 v3(68.475,30.65)
  other v1: 68.475,30.65
PC9: U14.V6 | length 0.6
  Signal Layer 2 w0.075: 68.475,29.6 v3(68.475,30.15)
  other v1: 68.475,30.15
PC10: U14.W6 | length 0.4
  Top Layer w0.075: 68.475,29.275 U14.W6@68.475,29.65
PC11: U14.V5 | length 0.6
  Signal Layer 2 w0.075: 67.975,29.6 v3(67.975,30.15)
  other v1: 67.975,30.15
PC12: U14.V4 | length 0.5
  Signal Layer 2 w0.075: 67.475,29.625 v1(67.475,30.15)
  other v3: 67.475,30.15
PCIE_CLKINTN: U14.V13 | length 0.4
  Signal Layer 2 w0.075: 71.975,29.725 v3(71.975,30.15)
  other v1: 71.975,30.15
PCIE_CLKINTP: U14.U13 | length 1.1
  Signal Layer 2 w0.075: 71.726,29.665 71.726,30.253 71.941,30.469 71.941,30.616 v3(71.975,30.65)
  other v1: 71.975,30.65
PCIE_CLKOUTN: U14.U14 | length 1
  Signal Layer 2 w0.075: 72.225,29.75 72.225,30.4 v3(72.475,30.65)
  other v1: 72.475,30.65
PCIE_CLKOUTP: U14.V14 | length 0.5
  Signal Layer 2 w0.075: 72.45,29.675 72.45,30.125 v3(72.475,30.15)
  other v1: 72.475,30.15
PD0: U14.C11 | length 1.6
  Signal Layer 2 w0.075: v3@70.947,37.678 v3(70.975,37.65) 71.01,37.685 71.01,37.833 71.225,38.047 71.225,39.15
  other v1: 70.975,37.65
PD1: U14.F9 | length 2.7
  Signal Layer 2 w0.075: v3(69.975,36.15) 69.975,37.297 70.226,37.548 70.226,37.792 70.395,37.962 70.395,38.402 70.48,38.487 70.48,38.625
  other v1: 69.975,36.15
PD2: U14.A10 | length 0.5
  Top Layer w0.075: U14.A10@70.475,38.65 70.475,39.125
PD3: U14.D8 | length 2
  Signal Layer 2 w0.075: v3(69.475,37.15) 69.725,37.4 69.725,39
  other v1: 69.475,37.15
PD4: U14.C12 | length 1
  Signal Layer 2 w0.075: v3(71.475,37.65) 71.51,37.685 71.51,37.772 71.56,37.822 71.56,38.588
  other v1: 71.475,37.65
PD5: U14.B12 | length 1.1
  Top Layer w0.075: U14.B12@71.475,38.15 71.475,38.318 71.71,38.553 71.71,39.16 71.725,39.175
PD6: U14.A12 | length 0.5
  Top Layer w0.075: U14.A12@71.475,38.65 71.475,39.125
PD7: U14.D12 | length 1.2
  Signal Layer 2 w0.075: v3(71.475,37.15) 71.726,37.401 71.726,37.546 ; 71.726,37.547 71.726,38.253
  other v1: 71.475,37.15
PD8: U14.E11 | length 1.2
  Signal Layer 3 w0.075: v4(70.975,36.65) 70.975,37.875
  other v1: 70.975,36.65
PD9: U14.C10 | length 1.6
  Signal Layer 2 w0.075: v3@70.44,37.685 v3(70.475,37.65) 70.51,37.685 70.51,37.812 70.56,37.863 70.56,38.334 70.645,38.418 70.645,39.093
  other v1: 70.475,37.65
PD10: U14.D11 | length 2
  Signal Layer 2 w0.075: 70.81,39.025 70.81,38.35 70.725,38.266 70.725,37.547 70.94,37.333 70.94,37.185 v3(70.975,37.15)
  other v1: 70.975,37.15
PD11: U14.B10 | length 1.2
  Top Layer w0.075: 70.225,39.225 70.225,38.557 70.452,38.33 70.452,38.173 U14.B10@70.475,38.15
PD12: U14.H14 | length 0.9
  Signal Layer 3 w0.075: v4(72.475,35.15) 72.475,35.279 72.8,35.604 72.8,35.875
  other v1: 72.475,35.15
PD13: U14.G9 | length 4.1
  Top Layer w0.075: 69.725,39.35 69.725,38.047 69.872,37.901 69.925,37.901 69.926,37.9 70.078,37.9 70.225,37.753 70.225,35.908 69.975,35.659 U14.G9@69.975,35.65
PE0: U14.B13 | length 1
  Signal Layer 2 w0.075: v3(71.975,38.15) 71.975,39.175
  other v1: 71.975,38.15
PE1: U14.C13 | length 1.6
  Signal Layer 2 w0.075: v3(71.975,37.65) 72.01,37.685 72.01,37.833 72.225,38.047 72.225,39.1
  other v1: 71.975,37.65
PE2: U14.A14 | length 0.6
  Top Layer w0.075: 72.45,39.225 72.475,39.2 U14.A14@72.475,38.65
PE3: U14.A15 | length 0.5
  Top Layer w0.075: U14.A15@72.975,38.65 72.975,39.175
PE4: U14.B14 | length 0.8
  Signal Layer 1 w0.075: 72.2,38.817 72.2,38.425 v1(72.475,38.15)
PE5: U14.C14 | length 1.6
  Signal Layer 2 w0.075: v3(72.475,37.65) 72.475,37.7 72.56,37.785 72.56,38.743 72.562,38.746 72.562,39.19
  other v1: 72.475,37.65
PF0: U14.N9 | length 3.9
  Top Layer w0.075: 69.2,29.325 69.218,29.343 69.218,32.246 69.372,32.399 69.585,32.399 69.819,32.634 69.959,32.634 U14.N9@69.975,32.65
PF1: U14.U8 | length 1.5
  Signal Layer 2 w0.075: 69.226,29.301 69.226,30.253 69.452,30.48 69.452,30.627 v3(69.475,30.65)
  other v1: 69.475,30.65
PF2: U14.P9 | length 3.2
  Signal Layer 2 w0.075: 69.05,29.425 69.05,30.3 69.144,30.393 69.144,30.671 69.372,30.9 69.578,30.9 69.724,31.047 69.724,31.199 69.726,31.2 69.726,31.486 69.726,31.901 v3(69.975,32.15)
  other v1: 69.975,32.15
PF3: U14.W10 | length 0.5
  Top Layer w0.075: U14.W10@70.475,29.65 70.5,29.625 70.5,29.175
PF4: U14.W7 | length 0.3
  Top Layer w0.075: 68.975,29.35 U14.W7@68.975,29.65
PF5: U14.P7 | length 5
  Top Layer w0.075: 66.2,29.125 66.2,29.416 66.224,29.44 66.224,29.755 66.367,29.897 66.575,29.897 66.725,30.048 66.725,30.253 66.873,30.401 67.078,30.401 67.225,30.547 67.225,30.753 67.372,30.899 67.66,30.899 67.662,30.897 68.074,30.897 68.224,31.047 68.224,31.252 68.372,31.4 68.577,31.4 68.732,31.555 68.732,31.75 68.968,31.986 68.968,32.143 U14.P7@68.975,32.15
PF6: U14.U5 | length 2.3
  Top Layer w0.075: 66.725,29.15 66.74,29.165 66.74,29.542 66.732,29.55 66.732,29.75 66.875,29.892 66.886,29.892 66.891,29.897 67.075,29.897 67.225,30.047 67.225,30.253 67.372,30.4 67.578,30.4 67.816,30.638 67.963,30.638 U14.U5@67.975,30.65
PF7: U14.V7 | length 1
  Top Layer w0.075: 68.7,29.25 68.732,29.282 68.732,29.761 68.962,29.991 68.962,30.137 U14.V7@68.975,30.15
PF8: U14.U7 | length 1.8
  Top Layer w0.075: 68.2,29.275 68.232,29.307 68.232,29.75 68.383,29.901 68.578,29.901 68.732,30.055 68.732,30.256 68.965,30.488 68.965,30.64 U14.U7@68.975,30.65
PF9: U14.T6 | length 1.8
  Signal Layer 2 w0.075: 67.725,29.65 67.725,30.253 67.891,30.418 67.891,30.566 v3(68.475,31.15)
  other v1: 68.475,31.15
PF10: U14.L9 | length 5.1
  Top Layer w0.075: 65.675,32.4 66.578,32.4 66.725,32.548 66.725,32.753 66.872,32.9 67.078,32.9 67.225,33.047 67.225,33.253 67.373,33.4 69.725,33.4 U14.L9@69.975,33.65
PF11: U14.T4 | length 1.8
  Signal Layer 2 w0.075: 65.95,30.4 66.175,30.625 66.536,30.625 66.75,30.839 66.811,30.839 66.873,30.901 67.226,30.901 v3(67.475,31.15)
  other v1: 67.475,31.15
PF12: U14.L7 | length 4.2
  Top Layer w0.075: 64.875,33.9 68.578,33.9 68.628,33.85 68.775,33.85 U14.L7@68.975,33.65
PF13: U14.H2 | length 1.2
  Top Layer w0.075: 65.4,35.4 66.225,35.4 U14.H2@66.475,35.15
PF14: U14.G7 | length 5.2
  Top Layer w0.075: 66.226,39.117 66.226,38.753 66.226,38.547 66.372,38.4 66.55,38.4 66.551,38.399 66.578,38.399 66.724,38.253 66.724,38.226 ; U14.G7@68.973,35.652 68.947,35.678 68.947,35.835 68.732,36.05 68.732,36.245 68.578,36.399 68.312,36.399 68.225,36.486 68.225,36.753 68.078,36.9 67.872,36.9 67.725,37.047 67.725,37.252 67.577,37.401 67.372,37.401 67.225,37.547 67.225,37.753 67.077,37.901 66.872,37.901 66.726,38.047 66.726,38.225 ; 66.724,38.226 66.726,38.225
PF15: U14.G5 | length 1
  Signal Layer 3 w0.075: 66.967,35.65 v4(67.975,35.65)
  other v1: 67.975,35.65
